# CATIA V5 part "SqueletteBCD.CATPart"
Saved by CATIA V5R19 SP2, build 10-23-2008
Part number: SqueletteBCD
Publications: "AxeD", "PointD", "PointC", "BodyBCD", "RayonTrouBCD"
Bounding box of the stored display mesh (mm): x -20 to 0, y 8 to 93.207, z 110 to 183.207
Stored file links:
  D:\France\IFMA\IAO\Projet\SqueletteBCD.CATPart
  D:\France\IFMA\IAO\Projet\pruangdaja_CAO.CATProduct
  D:\France\IFMA\IAO\Projet\SquelettePrin.CATPart
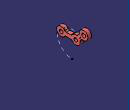
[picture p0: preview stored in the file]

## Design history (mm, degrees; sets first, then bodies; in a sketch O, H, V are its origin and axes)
Parameters
  RayonTrouBCD = 5 mm {= External.LargeurBCD /2}
External parameters (linked from other documents)
  External.LongueurCD = 30 mm
  External.LongueurBD = 40 mm
  External.Largeur = 10 mm
  External.LongueurB = 20 mm
  External.HauteurB = 150 mm
  External.RayonTrou = 5 mm
  External.LargeurBCD = 10 mm
Set1
  Plane1: linked copy from another document
  Point1: linked copy from another document
  Point2: linked copy from another document
Set2
  Point3: (0, 60 {= External.LongueurBD +External.LongueurB}, 150 {= External.HauteurB})
  Line1: type PtDir, RefPoint Point3, Direction (1, 0, 0), Start -20, End 20
  Circle1: type CtrRad, Start 45, End 135, Center Point3, Support Plane1, Radius 30 {= External.LongueurCD}, FirstDirection (0, 1, 0)
  Circle2: type CtrRad, Start 180, End 270, Center Point3, Support Plane1, Radius 40 {= External.LongueurBD}, FirstDirection (0, 1, 0)
  Point4: (0, 21.2132 {= External.LongueurCD *cos(45deg)}, 21.2132 {= External.LongueurCD *sin(45deg)}), relative to Point3
  Line2: type PtPt, FirstPoint Point3, SecondPoint Point4
  Line3: type PtPt, FirstPoint Point3, SecondPoint Point2
  Plane2: type Offset, RefPlane Plane1, Offset 10 {= 10mm}, reversed
  Sketch1 on Plane2, origin (-10, 0, 0), H (0, 1, 0), V (0, 0, 1)
    arc A1 centre (81.2132, 171.2132) radius 12 from (79.3426, 159.3599) to (69.3599, 169.3426) ccw
    arc A2 centre (60, 150) radius 12 from (50.2957, 142.9412) to (71.8533, 151.8706) ccw
    arc A3 centre (20, 150) radius 12 from (29.7043, 157.0588) to (29.7043, 142.9412) ccw
    circle A4 centre (81.2132, 171.2132) radius 5
    circle A5 centre (60, 150) radius 5
    circle A6 centre (20, 150) radius 5
    point P1 (84.7487, 167.6777)
    line L1 (75.0276, 157.9566) -> (73.2566, 156.1856)
    point P2 (63.5355, 146.4645)
    line L2 (67.9566, 165.0276) -> (66.1856, 163.2566)
    point P3 (56.4645, 153.5355)
    arc A7 centre (78.5632, 154.421) radius 5 from (75.0276, 157.9566) to (79.3426, 159.3599) cw
    arc A8 centre (76.7922, 152.65) radius 5 from (71.8533, 151.8706) to (73.2566, 156.1856) cw
    line L3 (46.2523, 145) -> (33.7477, 145)
    line L4 (33.7477, 155) -> (46.2523, 155)
    point P9 (20, 155)
    point P10 (60, 155)
    arc A9 centre (33.7477, 160) radius 5 from (29.7043, 157.0588) to (33.7477, 155) ccw
    arc A10 centre (33.7477, 140) radius 5 from (33.7477, 145) to (29.7043, 142.9412) ccw
    arc A11 centre (46.2523, 160) radius 5 from (46.2523, 155) to (50.2957, 157.0588) ccw
    arc A12 centre (46.2523, 140) radius 5 from (46.2523, 145) to (50.2957, 142.9412) cw
    arc A13 centre (64.421, 168.5632) radius 5 from (67.9566, 165.0276) to (69.3599, 169.3426) ccw
    arc A14 centre (62.65, 166.7922) radius 5 from (66.1856, 163.2566) to (61.8706, 161.8533) cw
    point P26 (61.8706, 161.8533)
    arc A15 centre (60, 150) radius 12 from (61.8706, 161.8533) to (50.2957, 157.0588) ccw
    radius A3 = 12 {= External.LargeurBCD +2mm}
    radius A2 = 12 {= Sketch1.radius(A3)}
    radius A1 = 12 {= Sketch1.radius(A3)}
    radius A6 = 5 {= External.LargeurBCD /2}
    distance L1 L2 = 10 {= External.LargeurBCD}
    radius A7 = 5
    radius A8 = 5
    radius A9 = 5
    radius A10 = 5
    radius A11 = 5
    radius A12 = 5
    radius A13 = 5
    radius A14 = 5
    coincidence: P1 A4, P2 A5, P3 A5, L1 P1, L1 P2, P9 A6, P10 A5, L4 P9, L4 P10, L2 P3, P26 A2, A2 A15
    tangency: L1 A5, L1 A4, L2 A4, L2 A5, A7 L1, A7 A1, A8 A2, A8 L1, L3 A6, L3 A5, L4 A5, A6 L4, A9 A3, A9 L4, A10 L3, A10 A3, A11 L4, A11 A2, A12 L3, A12 A2, A13 L2, A13 A1, A14 L2, A14 A2
Body1 (main body)
  Pad1: profile Sketch1, direction (-1, 0, 0), length 10 {= External.LargeurBCD}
